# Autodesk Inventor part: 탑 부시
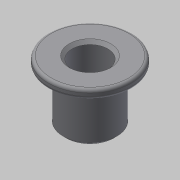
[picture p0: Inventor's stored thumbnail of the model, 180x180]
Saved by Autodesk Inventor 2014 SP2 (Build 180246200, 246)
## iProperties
Created: 2016-08
Part Number: 탑 부시
Material: 스테인리스강
Document SubType Name: Modeling
Designer: mduedu
Density: 8.08 g/cm^3
Appearance: 기본값
Author: mduedu
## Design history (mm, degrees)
sketch "스케치1"
  geometry: L1 (0, 0)-(9, 0); L2 (9, 0)-(9, 17); L3 (0, 20)-(0, 0); L4 (9, 17)-(14, 17); L5 (14, 17)-(14, 20); L6 (14, 20)-(0, 20)
  constraints: 12 end point, 2 horizontal, 2 parallel, 2 perpendicular
  dimensions: "d0" = 9 distance between parallel lines of L2 L3; "d2" = 20 distance of L3.start L1.start; "d3" = 14 distance between parallel lines of L5 L3; "d4" = 3 distance of L4.end L5.end
revolve "회전1" sketch "스케치1" stored, may be unused: angle "d5" = 90 deg
hole "구멍1" diameter "d8" = 12; stored, may be unused: countersink angle "d12" = 90 deg, drill point angle "d14" = 118 deg; dims "d6" = 10, "d7" = 10, "d9" = 6, "d10" = 4, "d11" = 2, "d13" = 8
chamfer "모따기1" distance "d15" = 1; stored, may be unused: second distance "d16" = 2, angle "d17" = 45 deg
fillet "모깎기1" dims "d18" = 1
node "솔리드1"
